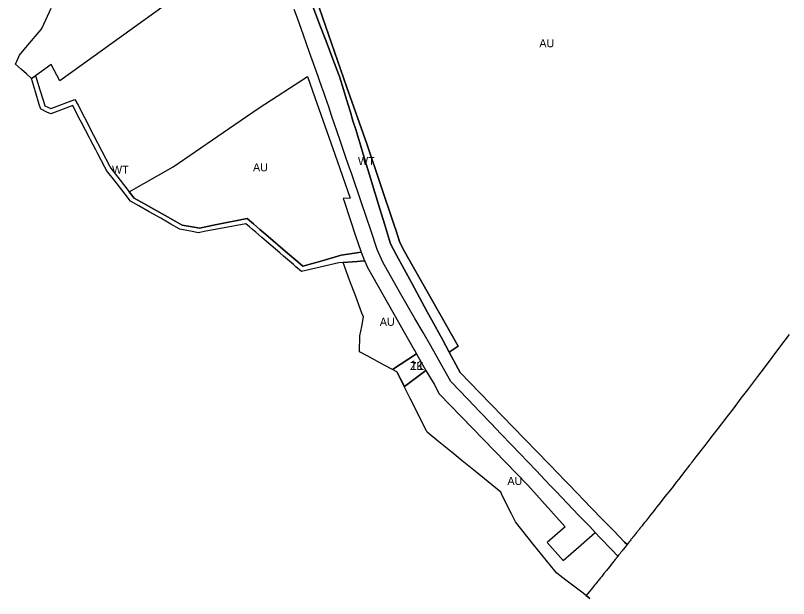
# Model space of a CAD drawing. Extents: x -537068 to -534056, y -1176840 to -1172401.
# Drawn here: x -537023.4 to -536540.8, y -1174945.9 to -1174581.9 of the extents above; entities that cross this region are included whole.
import ezdxf

# ---------------------------------------------------------------- set-up
doc = ezdxf.new("R2010")
doc.units = 0
for name, color, linetype in [('90640013', 7, 'Continuous'), ('90710023', 7, 'Continuous'), ('90750013', 7, 'Continuous'), ('ID_navrh', 7, 'Continuous')]:
    doc.layers.add(name, color=color, linetype=linetype)

msp = doc.modelspace()

# ---------------------------------------------------------------- linework, layer by layer
at = {"layer": '90640013'}
msp.add_lwpolyline([(-536837.45, -1174577.47), (-536833.4, -1174588), (-536829.53, -1174598.09), (-536825.27, -1174609.19), (-536821.47, -1174619.05), (-536821.35, -1174619.37), (-536819.28, -1174626.16), (-536817.43, -1174632.24), (-536815.78, -1174637.65), (-536814.38, -1174642.24), (-536812.72, -1174647.7), (-536811.05, -1174653.16), (-536807.87, -1174663.59), (-536806.4, -1174668.42), (-536804.3, -1174675.31), (-536801.82, -1174683.44), (-536799.06, -1174692.48), (-536795.95, -1174702.67), (-536793.09, -1174712.05), (-536789.29, -1174724.52), (-536785.46, -1174731.59), (-536775.98, -1174749.09), (-536766.33, -1174766.9), (-536761.47, -1174775.86), (-536756.9, -1174784.28), (-536752.61, -1174792.19), (-536747.05, -1174802.46), (-536745.77, -1174804.82), (-536733.55, -1174817.43), (-536726.4, -1174824.81), (-536719.22, -1174832.21), (-536712.97, -1174838.66), (-536705.49, -1174846.38), (-536690.51, -1174861.83), (-536684.3, -1174868.23), (-536681.06, -1174871.57), (-536677.6, -1174875.14), (-536663.98, -1174889.19), (-536656.86, -1174896.53), (-536649.7, -1174903.92), (-536643.2, -1174910.62), (-536641.63, -1174912.24), (-536642.19, -1174912.94), (-536642.86, -1174913.78), (-536644.07, -1174915.29), (-536644.09, -1174915.33), (-536644.15, -1174915.4), (-536644.21, -1174915.47), (-536644.25, -1174915.52), (-536644.3, -1174915.59), (-536644.39, -1174915.7), (-536644.47, -1174915.8), (-536644.56, -1174915.91), (-536644.65, -1174916.03), (-536644.72, -1174916.11), (-536644.8, -1174916.21), (-536644.87, -1174916.3), (-536644.93, -1174916.38), (-536645, -1174916.46), (-536645.08, -1174916.56), (-536645.18, -1174916.69), (-536645.28, -1174916.82), (-536645.6, -1174917.21), (-536645.77, -1174917.42), (-536645.95, -1174917.66), (-536646.16, -1174917.92), (-536646.5, -1174918.35), (-536646.89, -1174918.83), (-536647.36, -1174919.42), (-536651.12, -1174915.48), (-536658.32, -1174907.95), (-536661.56, -1174904.56), (-536664.96, -1174901.01), (-536671.86, -1174893.79), (-536685.97, -1174879.04), (-536689.34, -1174875.51), (-536692.66, -1174872.04), (-536698.47, -1174865.96), (-536713.63, -1174850.1), (-536720.34, -1174843.08), (-536726.48, -1174836.66), (-536733.51, -1174829.3), (-536740.95, -1174821.53), (-536751.55, -1174810.45), (-536754.29, -1174805.66), (-536764.23, -1174788.25), (-536769, -1174779.9), (-536774.06, -1174771.04), (-536783.59, -1174754.35), (-536794.07, -1174735.98), (-536797.54, -1174727.95), (-536801.4, -1174716.65), (-536804.55, -1174707.41), (-536807.68, -1174698.23), (-536813.53, -1174681.1), (-536815.69, -1174674.78), (-536817.34, -1174669.94), (-536820.76, -1174659.94), (-536822.6, -1174654.56), (-536824.45, -1174649.13), (-536826.1, -1174644.29), (-536827.9, -1174639.03), (-536829.94, -1174633.05), (-536830.96, -1174630.05), (-536832.15, -1174626.71), (-536835.8, -1174616.43), (-536839.8, -1174605.15), (-536843.67, -1174594.24), (-536847.43, -1174583.64), (-536849.37, -1174578.18)], dxfattribs=at)
msp.add_lwpolyline([(-536807.71, -1174729.63), (-536805.44, -1174735.08), (-536805.93, -1174735.11), (-536810.19, -1174735.55), (-536818.9, -1174736.2), (-536821.54, -1174736.38), (-536844.94, -1174741.74), (-536848.34, -1174738.82), (-536849.95, -1174737.44), (-536856.1, -1174732.15), (-536858.48, -1174730.1), (-536869.66, -1174720.49), (-536873.41, -1174717.27), (-536875.51, -1174715.46), (-536877.42, -1174713.82), (-536879.64, -1174711.91), (-536893.14, -1174714.49), (-536905.56, -1174716.87), (-536909.19, -1174717.56), (-536914.17, -1174716.62), (-536920.85, -1174715.36), (-536921.3, -1174715.1), (-536926.47, -1174712.15), (-536932.77, -1174708.56), (-536939.94, -1174704.47), (-536946.33, -1174700.82), (-536951.66, -1174697.78), (-536955.01, -1174693.5), (-536960.66, -1174686.27), (-536966.65, -1174678.61), (-536967.32, -1174677.31), (-536967.67, -1174676.64), (-536972, -1174668.3), (-536973.26, -1174665.88), (-536976.51, -1174659.63), (-536977.2, -1174658.29), (-536982.14, -1174648.79), (-536982.96, -1174647.2), (-536986.9, -1174639.63), (-536987.71, -1174638.07), (-537001.46, -1174643.33), (-537003.79, -1174642.23), (-537007.45, -1174640.49), (-537007.69, -1174640.38), (-537008.56, -1174637.5), (-537010.91, -1174629.7), (-537013.42, -1174621.34), (-537011.02, -1174619.61), (-537010.97, -1174619.67), (-537010.64, -1174620.11), (-537008.34, -1174627.74), (-537006.03, -1174635.43), (-537005.17, -1174638.29), (-537001.39, -1174640.08), (-537000.69, -1174639.81), (-536986.29, -1174634.31), (-536984.37, -1174638.01), (-536980.43, -1174645.6), (-536974.68, -1174656.67), (-536969.46, -1174666.7), (-536964.78, -1174675.71), (-536963.99, -1174677.23), (-536958.13, -1174684.69), (-536952.39, -1174692), (-536949.3, -1174695.93), (-536943.33, -1174699.29), (-536937.11, -1174702.79), (-536929.93, -1174706.82), (-536923.76, -1174710.29), (-536919.36, -1174712.76), (-536918.16, -1174712.97), (-536910.67, -1174714.29), (-536908.64, -1174714.65), (-536899.74, -1174712.87), (-536878.79, -1174708.68), (-536874.91, -1174712.01), (-536870.91, -1174715.45), (-536867.11, -1174718.72), (-536853.52, -1174730.41), (-536847.26, -1174735.79), (-536844.12, -1174738.49), (-536831.99, -1174735.05), (-536820.01, -1174731.65)], close=True, dxfattribs=at)
at = {"layer": '90710023'}
msp.add_lwpolyline([(-536835.56, -1174572.01), (-536816.72, -1174626.2), (-536804.01, -1174662.07), (-536786.98, -1174712.81), (-536785.77, -1174716.37), (-536783.63, -1174722.98), (-536781.34, -1174727.87), (-536747.07, -1174788.38), (-536752.61, -1174792.19), (-536756.9, -1174784.28), (-536761.47, -1174775.86), (-536766.33, -1174766.9), (-536775.98, -1174749.09), (-536785.46, -1174731.59), (-536789.29, -1174724.52), (-536793.09, -1174712.05), (-536795.95, -1174702.67), (-536799.06, -1174692.48), (-536801.82, -1174683.44), (-536804.3, -1174675.31), (-536806.4, -1174668.42), (-536807.87, -1174663.59), (-536811.05, -1174653.16), (-536812.72, -1174647.7), (-536814.38, -1174642.24), (-536815.78, -1174637.65), (-536817.43, -1174632.24), (-536819.28, -1174626.16), (-536821.35, -1174619.37), (-536821.47, -1174619.05), (-536825.27, -1174609.19), (-536829.53, -1174598.09), (-536833.4, -1174588), (-536837.45, -1174577.47)], dxfattribs=at)
msp.add_lwpolyline([(-536785.27, -1174804.29), (-536788.03, -1174802.83), (-536773.05, -1174793.18), (-536767.18, -1174803.45), (-536780.57, -1174813.49)], close=True, dxfattribs=at)
at = {"layer": '90750013'}
for points in [[(-536885.49, -1174543.27), (-536995.69, -1174622.76), (-537001.11, -1174612.47), (-537007.17, -1174616.84), (-537010.97, -1174619.67), (-537011.02, -1174619.61), (-537013.42, -1174621.34), (-537016.59, -1174618.48), (-537019.76, -1174615.62), (-537023.44, -1174612.3), (-537020.96, -1174606.77), (-537015.88, -1174600.67), (-537007.46, -1174590.61), (-537006.73, -1174589.74), (-537001.24, -1174577.3)], [(-536540.49, -1174781.02), (-536546.4, -1174789.03), (-536556.11, -1174801.9), (-536560.15, -1174807.24), (-536566.46, -1174815.57), (-536570.59, -1174820.91), (-536575.45, -1174827.55), (-536579.41, -1174832.4), (-536584.67, -1174839.44), (-536588.63, -1174844.54), (-536593, -1174850.36), (-536598.59, -1174857.48), (-536601.09, -1174860.66), (-536601.37, -1174861.02), (-536601.62, -1174861.35), (-536601.9, -1174861.7), (-536602.25, -1174862.13), (-536602.78, -1174862.8), (-536603.85, -1174864.22), (-536604.86, -1174865.53), (-536606.38, -1174867.43), (-536608.06, -1174869.62), (-536609.59, -1174871.58), (-536610.91, -1174873.26), (-536612.89, -1174875.89), (-536614.51, -1174877.99), (-536617.99, -1174882.2), (-536620.94, -1174886.06), (-536621.83, -1174887.2), (-536622.94, -1174888.63), (-536624.22, -1174890.21), (-536625.41, -1174891.77), (-536626.77, -1174893.47), (-536629.96, -1174897.51), (-536630.64, -1174898.39), (-536631.48, -1174899.43), (-536632.24, -1174900.39), (-536633.19, -1174901.6), (-536633.36, -1174901.81), (-536633.5, -1174901.99), (-536633.61, -1174902.14), (-536633.76, -1174902.32), (-536633.94, -1174902.54), (-536634.25, -1174902.94), (-536634.45, -1174903.19), (-536634.7, -1174903.51), (-536634.89, -1174903.74), (-536635.19, -1174904.12), (-536635.46, -1174904.47), (-536635.67, -1174904.73), (-536636.05, -1174905.2), (-536636.22, -1174905.42), (-536636.43, -1174905.68), (-536636.61, -1174905.91), (-536636.87, -1174906.25), (-536636.98, -1174906.38), (-536637.08, -1174906.5), (-536637.16, -1174906.61), (-536637.26, -1174906.73), (-536637.28, -1174906.75), (-536637.3, -1174906.79), (-536637.33, -1174906.82), (-536637.36, -1174906.86), (-536637.38, -1174906.89), (-536637.41, -1174906.92), (-536637.44, -1174906.96), (-536637.46, -1174906.99), (-536637.54, -1174907.09), (-536637.58, -1174907.13), (-536637.61, -1174907.17), (-536637.64, -1174907.22), (-536637.68, -1174907.27), (-536637.74, -1174907.34), (-536637.78, -1174907.39), (-536638.16, -1174907.86), (-536638.53, -1174908.33), (-536638.99, -1174908.91), (-536639.26, -1174909.25), (-536639.78, -1174909.91), (-536639.98, -1174910.16), (-536640.3, -1174910.57), (-536641.59, -1174912.18), (-536641.63, -1174912.24), (-536643.2, -1174910.62), (-536649.7, -1174903.92), (-536656.86, -1174896.53), (-536663.98, -1174889.19), (-536677.6, -1174875.14), (-536681.06, -1174871.57), (-536684.3, -1174868.23), (-536690.51, -1174861.83), (-536705.49, -1174846.38), (-536712.97, -1174838.66), (-536719.22, -1174832.21), (-536726.4, -1174824.81), (-536733.55, -1174817.43), (-536745.77, -1174804.82), (-536747.05, -1174802.46), (-536752.61, -1174792.19), (-536747.07, -1174788.38), (-536781.34, -1174727.87), (-536783.63, -1174722.98), (-536785.77, -1174716.37), (-536786.98, -1174712.81), (-536804.01, -1174662.07), (-536816.72, -1174626.2), (-536835.56, -1174572.01)]]:
    msp.add_lwpolyline(points, dxfattribs=at)
for points in [[(-536807.71, -1174729.63), (-536820.01, -1174731.65), (-536831.99, -1174735.05), (-536844.12, -1174738.49), (-536847.26, -1174735.79), (-536853.52, -1174730.41), (-536867.11, -1174718.72), (-536870.91, -1174715.45), (-536874.91, -1174712.01), (-536878.79, -1174708.68), (-536899.74, -1174712.87), (-536908.64, -1174714.65), (-536910.67, -1174714.29), (-536918.16, -1174712.97), (-536919.36, -1174712.76), (-536923.76, -1174710.29), (-536929.93, -1174706.82), (-536937.11, -1174702.79), (-536943.33, -1174699.29), (-536949.3, -1174695.93), (-536952.39, -1174692), (-536925, -1174676.38), (-536883.18, -1174647.74), (-536871.37, -1174639.66), (-536841.1, -1174619.95), (-536836.56, -1174633.08), (-536824.01, -1174668.43), (-536814.54, -1174695.99), (-536818.87, -1174696.2), (-536818.3, -1174697.92), (-536810.85, -1174720.21), (-536809.68, -1174723.6)], [(-536805.44, -1174735.08), (-536805.19, -1174735.68), (-536803.79, -1174738.89), (-536774.51, -1174790.62), (-536774.18, -1174791.2), (-536773.05, -1174793.18), (-536788.03, -1174802.83), (-536793.19, -1174800.11), (-536803.5, -1174794.66), (-536808.66, -1174791.94), (-536808.37, -1174781.86), (-536807.3, -1174775.99), (-536806.24, -1174770.13), (-536807.11, -1174767.79), (-536810.98, -1174757.42), (-536814.85, -1174747.06), (-536818.9, -1174736.2), (-536810.19, -1174735.55), (-536805.93, -1174735.11)], [(-536647.36, -1174919.42), (-536647.46, -1174919.54), (-536649.1, -1174921.6), (-536650.69, -1174923.6), (-536651.59, -1174924.68), (-536652.46, -1174925.78), (-536653.63, -1174927.29), (-536654.54, -1174928.39), (-536656.02, -1174930.25), (-536657.46, -1174932.04), (-536657.79, -1174932.45), (-536658.33, -1174933.11), (-536658.84, -1174933.75), (-536659.18, -1174934.18), (-536659.66, -1174934.77), (-536660.09, -1174935.3), (-536660.5, -1174935.81), (-536661.13, -1174936.6), (-536661.92, -1174937.56), (-536663.21, -1174939.22), (-536667.13, -1174944.05), (-536664.85, -1174945.87), (-536669.93, -1174941.93), (-536673.25, -1174939.4), (-536679.81, -1174934.4), (-536685.44, -1174930.11), (-536686.75, -1174928.49), (-536700.15, -1174911.9), (-536711.31, -1174898.08), (-536713.87, -1174892.9), (-536715.97, -1174888.64), (-536720.02, -1174880.45), (-536720.48, -1174879.51), (-536736.27, -1174866.65), (-536744.62, -1174859.85), (-536750.81, -1174854.81), (-536759.14, -1174848.02), (-536766.46, -1174842.06), (-536766.92, -1174841.14), (-536776.98, -1174820.94), (-536785.27, -1174804.29), (-536780.57, -1174813.49), (-536767.18, -1174803.45), (-536762.07, -1174812.08), (-536758.86, -1174818.06), (-536703.62, -1174875.13), (-536680.18, -1174901.02), (-536691.41, -1174910.96), (-536681.47, -1174922.19), (-536670.24, -1174912.25), (-536661.56, -1174904.56), (-536658.32, -1174907.95), (-536651.12, -1174915.48)]]:
    msp.add_lwpolyline(points, close=True, dxfattribs=at)

# ---------------------------------------------------------------- texts
at = {"layer": '90640013'}
for rotation, p in [(0, (-536809.57, -1174675.35)), (360, (-536963.16, -1174680.67))]:
    msp.add_text('WT', height=5, rotation=rotation, dxfattribs=at).set_placement(p)
at = {"layer": '90710023'}
msp.add_text('ZK', height=5, rotation=360, dxfattribs=at).set_placement((-536777.16, -1174803.33))
at = {"layer": '90750013'}
for p in [(-536696.38, -1174601.8), (-536716.31, -1174874.98)]:
    msp.add_text('AU', height=5, dxfattribs=at).set_placement(p)
for rotation, p in [(360, (-536875.14, -1174679.22)), (0, (-536795.97, -1174775.67))]:
    msp.add_text('AU', height=5, rotation=rotation, dxfattribs=at).set_placement(p)
at = {"layer": 'ID_navrh'}
msp.add_text('11', height=6, rotation=360, dxfattribs=at).set_placement((-536777.16, -1174803.33))

doc.saveas('drawing.dxf')
